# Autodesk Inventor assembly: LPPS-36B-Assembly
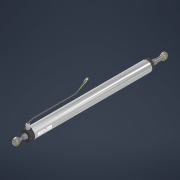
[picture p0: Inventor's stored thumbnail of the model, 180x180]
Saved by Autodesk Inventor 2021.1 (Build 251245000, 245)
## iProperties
Created: 2020-09
Part Number: LPPS-36B-Assembly
Document SubType Name: Assembly
Designer: J. Nielson
Author: J. Nielson
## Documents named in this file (3)
- C:\Users\Justin\Documents\CAD\The Sensor Connection\LPPS\LPPS-36B Series\3D\LPPS 36B-350\LPPS-36B-Assembly.iam
- C:\Users\Justin\Documents\CAD\The Sensor Connection\LPPS\LPPS-36B Series\3D\LPPS 36B-350\LPPS 36B-350_Shrinkwrap.ipt
- C:\Users\Justin\Documents\CAD\The Sensor Connection\LPPS\LPPS-36B Series\3D\LPPS 36B-350\LPPS 36B-350_Shaft_Shrinkwrap.ipt
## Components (2 placed, 2 different names)
1. LPPS 36B-350_Shrinkwrap:1 — Mate:1, Cylindrical:1, Angle:1
2. LPPS 36B-350_Shaft_Shrinkwrap:1 — Mate:1, Cylindrical:1, Angle:1
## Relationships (3: Mate 1, CylindricalJoint 1, Angle 1)
- Mate:1: LPPS 36B-350_Shrinkwrap:1 ↔ LPPS 36B-350_Shaft_Shrinkwrap:1
- Cylindrical:1: LPPS 36B-350_Shrinkwrap:1 ↔ LPPS 36B-350_Shaft_Shrinkwrap:1
- Angle:1: LPPS 36B-350_Shrinkwrap:1 ↔ LPPS 36B-350_Shaft_Shrinkwrap:1
